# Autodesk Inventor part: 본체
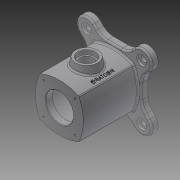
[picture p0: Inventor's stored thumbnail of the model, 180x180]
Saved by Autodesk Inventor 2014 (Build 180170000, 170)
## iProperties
Created: 2016-05
Part Number: 본체
Material: 일반
Document SubType Name: Modeling
Designer: J.H.Beak
Density: 1 g/cm^3
Appearance: 기본값
Author: J.H.Beak
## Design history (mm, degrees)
sketch "스케치1"
  geometry: L1 (35.355, -35.355)-(-35.355, -35.355); L2 (-35.355, -35.355)-(-35.355, 35.355); L3 (-35.355, 35.355)-(35.355, 35.355); L4 (35.355, 35.355)-(35.355, -35.355); L5 (35.355, -35.355)-(-35.355, 35.355); L6 (-35.355, -35.355)-(35.355, 35.355); A1 r 85.579 centre (-42.579, 0) between (35.355, -35.355) and (35.355, 35.355); A2 r 85.579 centre (0, -42.579) between (35.355, 35.355) and (-35.355, 35.355); A3 r 85.579 centre (42.579, 0) between (-35.355, 35.355) and (-35.355, -35.355); A4 r 85.579 centre (0, 42.579) between (-35.355, -35.355) and (35.355, -35.355); 3 further points
  constraints: 12 end point, 8 point on circle, 4 centre point, 4 midpoint, 3 equal radius, 2 parallel, 2 perpendicular, 1 horizontal, 1 horizontal alignment
  dimensions: "d0" = 100 distance of L1.start L2.end; "d3" = 86 dimension on A3 A1
extrude "돌출1" new body sketch "스케치1" distance "d4" = 98; taper "d5" = 0 deg
fillet "모깎기1" dims "d6" = 3
sketch "스케치2"
  geometry: L1 (0, 0)-(-49.497, -49.497); L2 (-67.249, 0)-(61.375, 0) reference; L3 (49, -49)-(-49, -49); L4 (-49, -49)-(-49, 49); L5 (-49, 49)-(49, 49); L6 (49, 49)-(49, -49); L7 (49, -49)-(-49, 49); L8 (-49, -49)-(49, 49); L9 (-49.497, -49.497)-(0, 0); L10 (-62.225, -36.77)-(-12.728, 12.728); L11 (12.728, -12.728)-(-36.77, -62.225); A1 r 18 centre (-49.497, -49.497) between (-62.225, -36.77) and (-36.77, -62.225); A2 r 18 centre (0, 0) between (12.728, -12.728) and (-12.728, 12.728); 1 further point
  constraints: 22 end point, 4 equal length, 4 point on circle, 4 tangent, 3 midpoint, 2 centre point, 2 perpendicular, 1 horizontal
  dimensions: "d8" = 45 deg angle of L2 L1; "d9" = 70 distance of L1.start L1.end; "d10" = 98 distance of L4.end L5.end; "d11" = 36 distance between parallel lines of L10 L11
extrude "돌출2" join sketch "스케치2" distance "d12" = 12; taper "d13" = 0 deg
fillet "모깎기2" dims "d17" = 25
node "작업 평면1"
sketch "스케치3"
  geometry: L1 (-36.77, 12)-(-67.497, 12) reference; C1 r 20 at (0, -49); 2 further points
  constraints: 1 centre point, 1 vertical alignment
  dimensions: "d19" = 61 distance from line of L1 C1.centre; "d20" = 40 diameter of C1
extrude "돌출3" join sketch "스케치3" stored distance "d21" = 12; taper "d22" = 10 deg
sketch "스케치4"
  geometry: L1 (-98, 0)-(-86, 0); L2 (-86, 0)-(-86, 25); L3 (-86, 25)-(-98, 25); L4 (-98, 25)-(-98, 0); L5 (-86, 0)-(0, 0); L6 (0, 0)-(0, 35); L7 (0, 35)-(-86, 35); L8 (-86, 35)-(-86, 0); L9 (0, 0)-(12, 0); L10 (12, 0)-(12, 25); L11 (12, 25)-(0, 25); L12 (0, 25)-(0, 0); L13 (-98, 34.285)-(-98, -34.285) reference; L14 (12, -13.189)-(12, 13.189) reference; L15 (0, -34.285)-(0, 34.285) reference; 2 further points
  constraints: 24 end point, 6 parallel, 3 horizontal, 3 perpendicular, 2 collinear, 1 midpoint, 1 point on line
  dimensions: "d23" = 12 distance of L2.end L3.end; "d24" = 86 distance of L6.end L7.end; "d25" = 70 diameter of L7 L5; "d26" = 50 diameter of L11 L5; "d27" = 50 diameter of L3 L5
revolve "회전1" sketch "스케치4" stored, may be unused: angle "d28" = 90 deg
hole "구멍1" diameter "d31" = 25; stored, may be unused: countersink angle "d35" = 90 deg, drill point angle "d37" = 118 deg; dims "d29" = 10, "d30" = 10, "d32" = 6, "d33" = 30, "d34" = 8, "d36" = 8
chamfer "모따기1" distance "d38" = 1; stored, may be unused: second distance "d39" = 2, angle "d40" = 45 deg
fillet "모깎기3" dims "d41" = 3
fillet "모깎기4" dims "d42" = 3
fillet "모깎기5" dims "d43" = 3
fillet "모깎기6" dims "d44" = 3
hole "구멍2" diameter "d47" = 10; stored, may be unused: countersink angle "d51" = 90 deg, drill point angle "d53" = 118 deg; dims "d45" = 10, "d46" = 10, "d48" = 6, "d49" = 18, "d50" = 4, "d52" = 8
sketch "스케치5"
  geometry: L1 (0, 0)-(28.284, 28.284); L2 (-94.496, 0)-(94.496, 0) reference
  constraints: 2 end point
  dimensions: "d57" = 45 deg angle of L2 L1; "d58" = 40 distance of L1.start L1.end
hole "구멍3" sketch "스케치5" at (28.284, 28.284) diameter "d59" = 3.242; stored, may be unused: countersink angle "d63" = 90 deg, drill point angle "d65" = 118 deg; dims "d60" = 7, "d61" = 18, "d62" = 4, "d64" = 10
node "작업 평면3"
sketch "스케치6"
  geometry: L1 (0, -71)-(0, 83) reference; L2 (-34.285, -49)-(34.285, -49) reference; 2 further points
  constraints: 1 other
  dimensions: "d69" = 29 distance from line of L1 point (29, 0); "d70" = 49 distance from line of L2 point (29, 0)
feature "엠보싱1" sketch "스케치6" dims "d0" = 100, "d3" = 86, "d10" = 98, "d71" = 0.5, "d72" = 0
node "솔리드1"
pattern_circular "원형 패턴1" dims angle "d15" = 360 deg
pattern_circular "원형 패턴2" dims angle "d55" = 360 deg
pattern_circular "원형 패턴3" dims angle "d67" = 360 deg
mirror "대칭2"
other parameters: "d18" = 55
